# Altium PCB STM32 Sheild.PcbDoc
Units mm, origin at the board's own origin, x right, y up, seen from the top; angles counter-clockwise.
Board outline 70 x 83 mm, 2 copper layers (Top Layer, Bottom Layer), stack 1.712 mm thick; 57 components, 56 nets, 326 pads, 25 vias.
Unrouted connection lines stored in the file: 12.
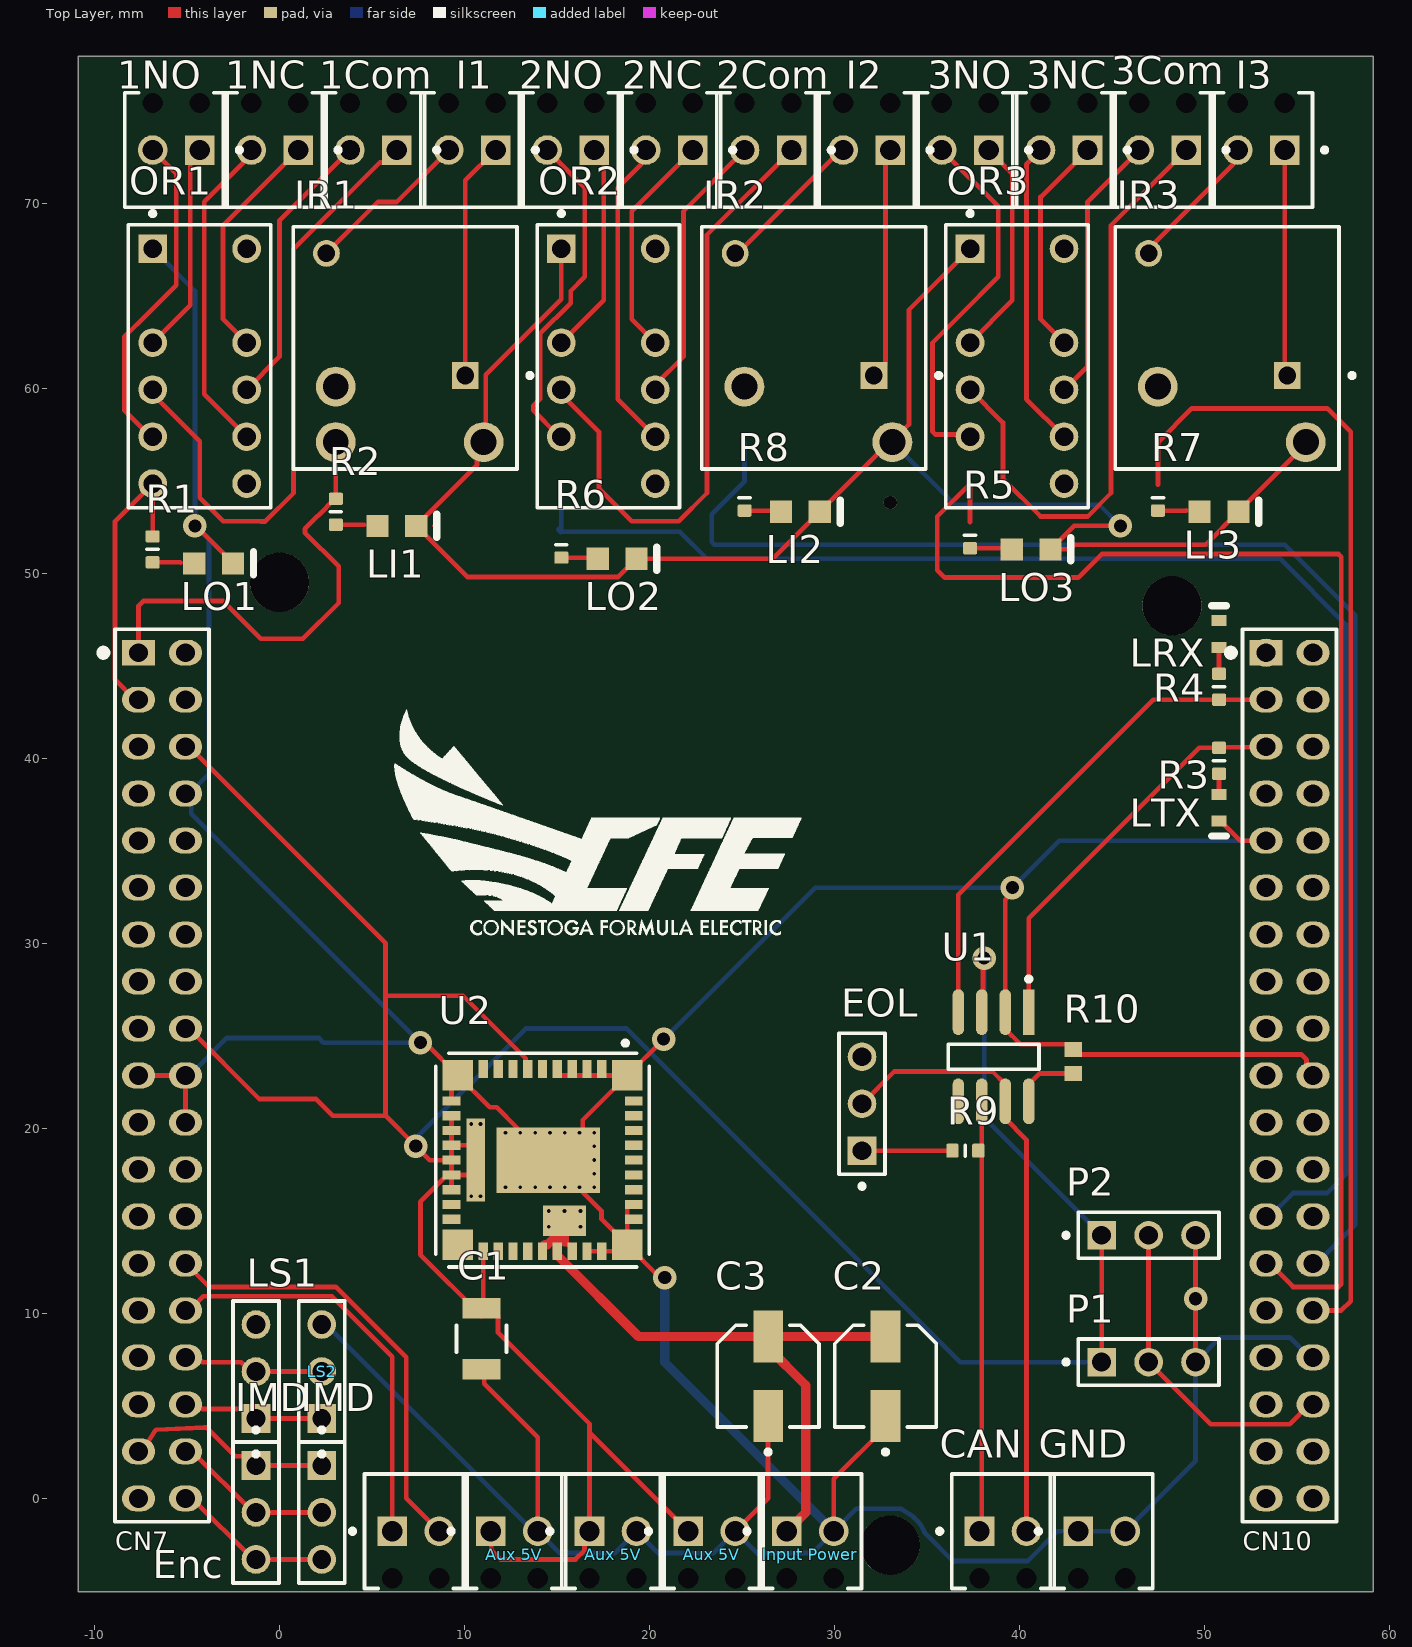
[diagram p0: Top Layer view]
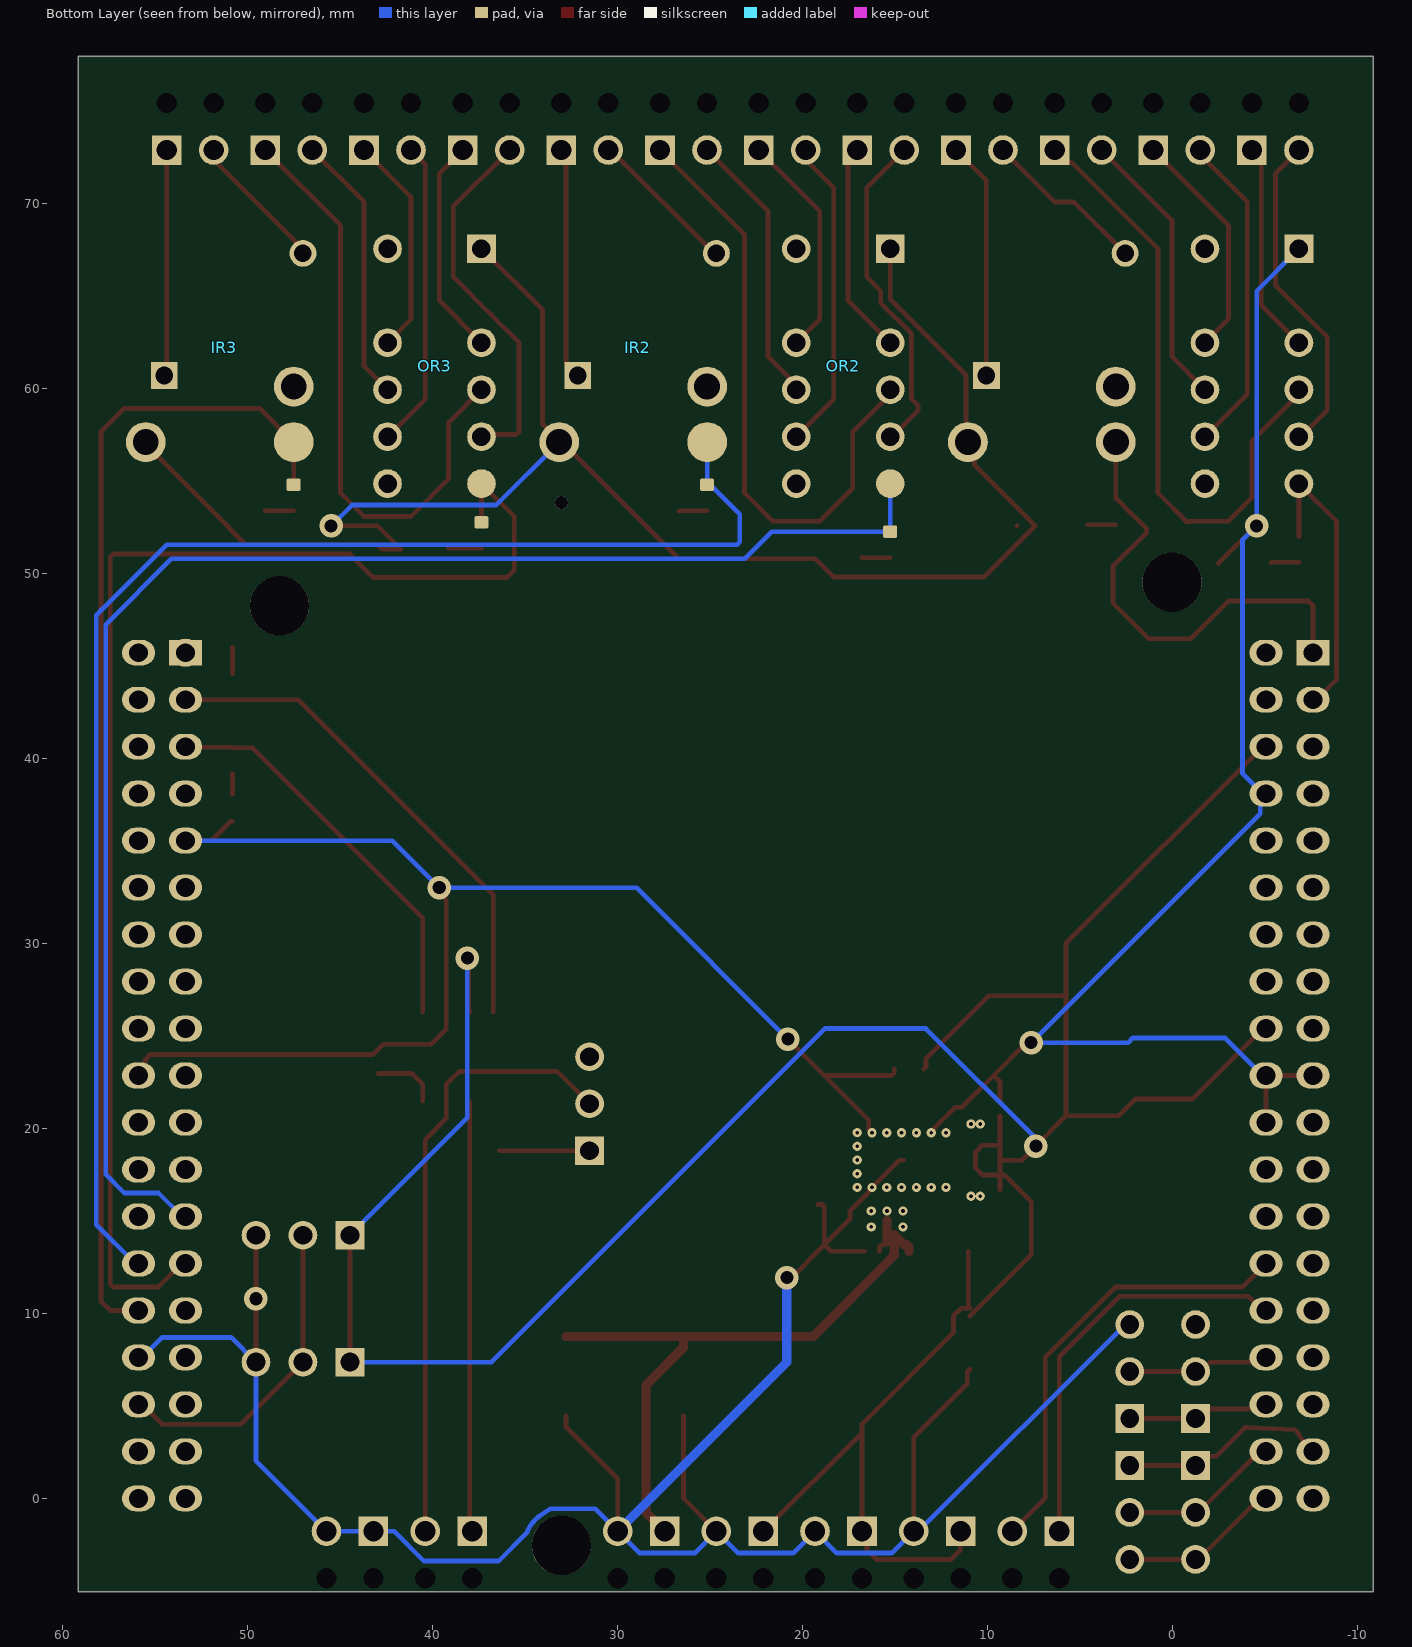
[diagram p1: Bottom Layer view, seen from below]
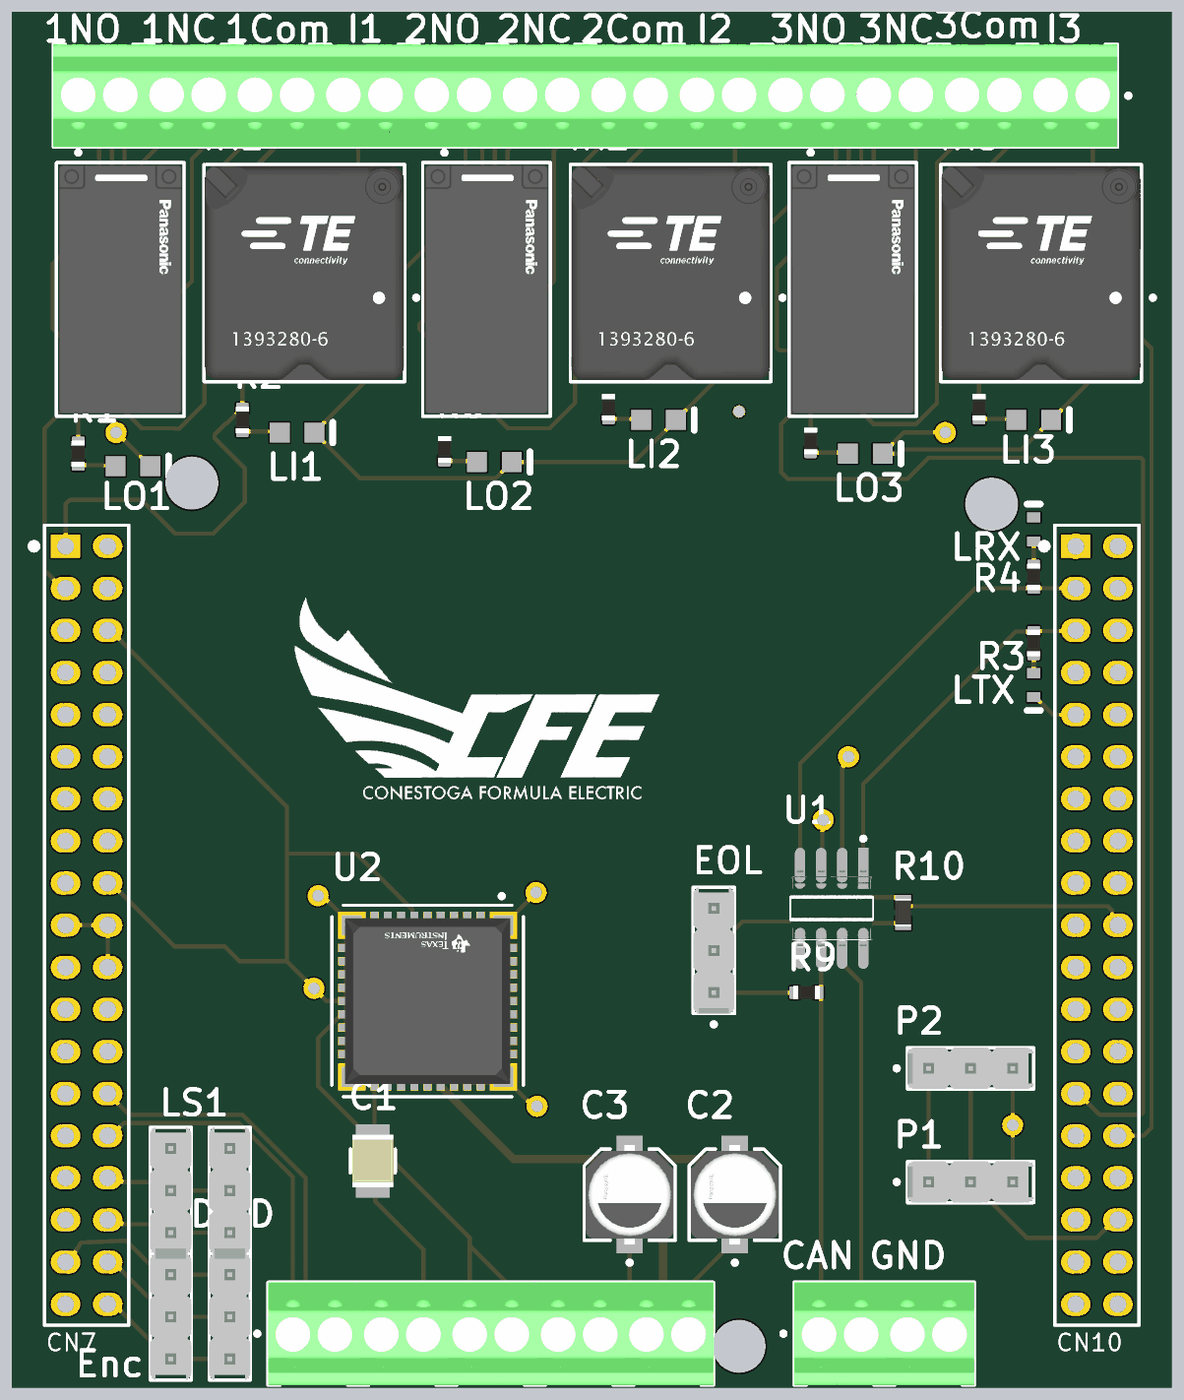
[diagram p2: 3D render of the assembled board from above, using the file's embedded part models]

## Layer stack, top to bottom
Top Solder: solder mask 0.0102, Solder Resist, Dk 3.5
Top Layer: signal copper 0.035
Dielectric 1: prepreg 0.0711, PP-006, Dk 4.1
Dielectric1: core 1.5, FR-4, Dk 4.8
Dielectric 4: prepreg 0.0711, PP-006, Dk 4.1
Bottom Layer: signal copper 0.035
Bottom Solder: solder mask 0.0102, Solder Resist, Dk 3.5

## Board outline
-10.87,-5.04 -10.87,77.96 59.13,77.96 59.13,-5.04 -10.87,-5.04

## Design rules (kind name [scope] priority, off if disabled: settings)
Clearance Clearance_1 [(InPoly)] p1: gap=0.381 ignorepadtopadclearanceinfootprint=FALSE
Clearance Clearance_2 [(HasFootprint('SB_DIP')) or (HasFootprint('JP2_SMD')) or InNet('PC13')] p2: gap=0.127 ignorepadtopadclearanceinfootprint=FALSE
Clearance [All] p3: gap=0.254 ignorepadtopadclearanceinfootprint=FALSE
FabricationTestPointUsage TestPointUsage [All] p1: valid=0 allowmultiple=FALSE
FabricationTestpoint Testpoint [(IsPad And (OnTopLayer Or OnBottomLayer))] p1: side=3 testpointundercomponent=TRUE minsize=1.016 maxsize=2.54 preferedsize=1.524 minholesize=0 maxholesize=1.016 preferedholesize=0.813 testpointgrid=0.025 allowsidetop=TRUE allowsidebottom=TRUE usegrid=TRUE gridtolerance=0
HoleSize [All] p1: absolutevalues=TRUE maxlimit=3.81 minlimit=0.025 maxpercent=80.000 minpercent=20.000
PolygonConnect PolygonConnect_1 [IsVia] p1: connectstyle=Direct reliefconductorwidth=0.508 reliefentries=4 polygonreliefangle="90 Angle" airgapwidth=0.254
PolygonConnect [All] p2: connectstyle=Relief reliefconductorwidth=0.508 reliefentries=4 polygonreliefangle="90 Angle" airgapwidth=0.254
RoutingLayers [All] p1: top layer_v5=FALSE bottom layer_v5=FALSE
RoutingVias [All] p1: holewidth=0.33 width=0.635 viastyle="Through Hole" minholewidth=0.203 minwidth=0.406 maxholewidth=0.711 maxwidth=1.27
SilkToSolderMaskClearance SilkscreenOverComponentPads [IsPad] p1: minsilkscreentomaskgap=0.254 clearancetoexposedcopper=TRUE
SolderMaskExpansion [All] p1: expansion=0.102 istentingtop=FALSE
SupplyNets "Schematic Supply Nets_1" [InNet('+5')] p1: voltage=0.000
SupplyNets "Schematic Supply Nets" [InNet('GND')] p2: voltage=0.000
Width Width_1 [InNet('VDD_MCU')] p1: maxlimit=2.54 minlimit=0.152 preferedwidth=0.305
Width [All] p2: maxlimit=2.54 minlimit=0.254 preferedwidth=0.254 minimp=50.000000 maximp=50.000000 favimp=50.000000
25 further rules are at their usual default settings.

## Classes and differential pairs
component class IMD: IMD
component class "Wheel Speed": "Aux 5V" Enc LS1 LS2
component class "Temp Sensors": P1 P2
component class Power: "5v Regulator" C1 C2 C3 Cin? Cin_? Cout? "Input Power" Rset? U2
component class "GPO Relays": 1Com 1NC 1NO 2Com 2NC 2NO 3Com 3NC 3NO "5v Regulator" Cin? Cin_? Cout? I1 I2 I3 IR1 IR2 IR3 OR1 OR2 OR3 Rset?
component class "MCU Connection": CN7 CN7b CN10 CN10b LI1 LI2 LO1 LO2 LO3 LRX LTX R1 R2 R3 R4 R5 R6 R7 R8
component class Comms: CAN EOL GND R9 R10 U1

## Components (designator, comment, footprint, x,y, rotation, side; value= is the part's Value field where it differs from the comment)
1Com "1725656" PHOE-1725656-2 5.08,72.898 r180 top
1NC "1725656" PHOE-1725656-2 -0.254,72.898 r180 top
1NO "1725656" PHOE-1725656-2 -5.588,72.898 r180 top
2Com "1725656" PHOE-1725656-2 26.416,72.898 r180 top
2NC "1725656" PHOE-1725656-2 21.082,72.898 r180 top
2NO "1725656" PHOE-1725656-2 15.748,72.898 r180 top
3Com "1725656" PHOE-1725656-2 47.752,72.898 r180 top
3NC "1725656" PHOE-1725656-2 42.418,72.898 r180 top
3NO "1725656" PHOE-1725656-2 37.084,72.898 r180 top
"Aux 5V" "1725656" PHOE-1725656-2 12.7,-1.778 r0 top
"Aux 5V" "1725656" PHOE-1725656-2 18.034,-1.778 r0 top
"Aux 5V" "1725656" PHOE-1725656-2 23.368,-1.778 r0 top
C1 "GRM32ER60J107ME20L" FP-GRM32-0_3-MFG 10.922,8.636 r270 top value=100uF
C2 "EEE-FK1H100UR" FP-FKC-MFG 32.766,6.604 r90 top
C3 "EEE-FK1H100UR" FP-FKC-MFG 26.416,6.604 r90 top
CAN "1725656" PHOE-1725656-2 39.116,-1.778 r0 top
CN7 "Header 19X2" 2*19P -7.62,45.72 r270 top locked
CN10 "Header 19X2" 2*19P 53.34,45.72 r270 top locked
Enc "1725656" PHOE-1725656-2 7.366,-1.778 r0 top
EOL "22-28-4033" MOLX-22-28-4033_V 31.496,21.336 r90 top
GND "1725656" PHOE-1725656-2 44.45,-1.778 r0 top
I1 "1725656" PHOE-1725656-2 10.414,72.898 r180 top
I2 "1725656" PHOE-1725656-2 31.75,72.898 r180 top
I3 "1725656" PHOE-1725656-2 53.086,72.898 r180 top
IMD "22-28-4033" MOLX-22-28-4033_V -1.27,-0.762 r270 top
IMD "22-28-4033" MOLX-22-28-4033_V 2.286,-0.762 r270 top
"Input Power" "1725656" PHOE-1725656-2 28.702,-1.778 r0 top
IR1 "1393280-6" FP-1393280-6-MFG#1 6.79,62.2 r180 top
IR2 "1393280-6" FP-1393280-6-MFG#2 28.888,62.2 r180 top
IR3 "1393280-6" FP-1393280-6-MFG#2 51.24,62.2 r180 top
LI1 "HSMG-C170" AVAG-HSMX-C170_V 6.35,52.578 r0 top
LI2 "HSMG-C170" AVAG-HSMX-C170_V 28.16,53.34 r0 top
LI3 "HSMG-C170" AVAG-HSMX-C170_V 50.8,53.34 r0 top
LO1 "HSMG-C170" AVAG-HSMX-C170_V -3.556,50.546 r0 top
LO2 "HSMG-C170" AVAG-HSMX-C170_V 18.254,50.8 r0 top
LO3 "HSMG-C170" AVAG-HSMX-C170_V 40.64,51.308 r0 top
LRX "TLMS1000-GS08" VISH-TLMS1000_V 50.8,46.736 r90 top
LS1 "22-28-4033" MOLX-22-28-4033_V -1.27,6.858 r90 top
LS2 "22-28-4033" MOLX-22-28-4033_V 2.286,6.858 r90 top
LTX "TLMS1000-GS08" VISH-TLMS1000_V 50.8,37.338 r270 top
OR1 "TX2-L2-5V" FP-TX2-L2-5V-MFG#1 -4.318,61.214 r270 top
OR2 "TX2-L2-5V" FP-TX2-L2-5V-MFG#2 17.78,61.214 r270 top
OR3 "TX2-L2-5V" FP-TX2-L2-5V-MFG#2 39.878,61.214 r270 top
P1 "22-28-4033" MOLX-22-28-4033_V 46.99,7.366 r0 top
P2 "22-28-4033" MOLX-22-28-4033_V 46.99,14.224 r0 top
R1 "Resistor 120R +/-5 % 0603 0.1 W" RESC0603(1608)_L#1 -6.858,51.308 r90 top value=120
R2 "Resistor 120R +/-5 % 0603 0.1 W" RESC0603(1608)_L#1 3.048,53.34 r90 top value=120
R3 "Resistor 120R +/-5 % 0603 0.1 W" RESC0603(1608)_L#1 50.8,39.878 r270 top value=120
R4 "Resistor 120R +/-5 % 0603 0.1 W" RESC0603(1608)_L#1 50.8,43.88 r90 top value=120
R5 "Resistor 120R +/-5 % 0603 0.1 W" RESC0603(1608)_L#2 37.338,52.07 r90 top value=120
R6 "Resistor 120R +/-5 % 0603 0.1 W" RESC0603(1608)_L#2 15.24,51.562 r90 top value=120
R7 "Resistor 120R +/-5 % 0603 0.1 W" RESC0603(1608)_L#2 47.498,54.102 r90 top value=120
R8 "Resistor 120R +/-5 % 0603 0.1 W" RESC0603(1608)_L#2 25.146,54.102 r90 top value=120
R9 "Resistor 120R +/-5 % 0603 0.1 W" RESC0603(1608)_L#1 37.084,18.796 r180 top value=120
R10 "CRCW060310K0FKEA" RESC1609X50X30NL8T20 42.926,23.622 r270 top
U1 "SN65HVD230DR" FP-D0008A-IPC_A 38.608,23.876 r270 top
U2 "LMZ34202RVQT" FP-RVQ0043E-MFG 14.224,18.288 r270 top

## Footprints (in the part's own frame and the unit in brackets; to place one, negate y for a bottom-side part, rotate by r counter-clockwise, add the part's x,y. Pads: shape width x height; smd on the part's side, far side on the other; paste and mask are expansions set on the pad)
2*19P [mil]
  rect 55x70 hole 40: 1(0,0)
  oval 55x70 hole 40: 2(0,100) 3(100,0) 4(100,100) 5(200,0) 6(200,100) 7(300,0) 8(300,100) 9(400,0) 10(400,100) 11(500,0) 12(500,100) 13(600,0) 14(600,100) 15(700,0) 16(700,100) 17(800,0) 18(800,100) 19(900,0) 20(900,100) 21(1000,0) 22(1000,100) 23(1100,0) 24(1100,100) 25(1200,0) 26(1200,100) 27(1300,0) 28(1300,100) 29(1400,0) 30(1400,100) 31(1500,0) 32(1500,100) 33(1600,0) 34(1600,100) 35(1700,0) 36(1700,100) 37(1800,0) 38(1800,100)
  silkscreen extent -50,-82 1850,150
AVAG-HSMX-C170_V [mm] "SMD, 2-Leads, Body 2x1.25mm, Height 0.8mm"
  rect 1.2x1.2 smd: 1(-1.05,0) 2(1.05,0)
  silkscreen extent 2.15,-0.63 2.15,0.62, body extent -1,-0.63 1,0.63, height 0.8
FP-1393280-6-MFG#1 [mm]
  rect 1.45x1.45 hole 0.95 paste-2539.97 mask+0: 1(-3.25,1.49)
  round 1.45 hole 0.95 paste-2539.97 mask+0: 2(4.25,-5.11)
  round 2.15 hole 1.4 paste-2539.97 mask+0: 3(3.75,5.09) 4(-4.25,5.09) 5(3.75,2.09)
  silkscreen extent -6.88,-6.55 6.05,6.55, body extent -6.15,-6.65 6.15,6.65, height 0.25
FP-1393280-6-MFG#2 [mm]
  rect 1.45x1.45 hole 0.95 paste-2539.97 mask+0: 1(-3.25,1.49)
  round 1.45 hole 0.95 paste-2539.97 mask+0: 2(4.25,-5.11)
  round 2.15 smd far side paste-2539.97 mask+0: 3(3.75,5.09)
  round 2.15 hole 1.4 paste-2539.97 mask+0: 4(-4.25,5.09) 5(3.75,2.09)
  silkscreen extent -6.88,-6.55 6.05,6.55, body extent -6.15,-6.65 6.15,6.65, height 0.25
FP-D0008A-IPC_A [mm]
  rect 2.469x0.622 smd paste+0 mask+0: 1(-2.414,1.905)
  rrect100% 2.469x0.622 smd paste+0 mask+0: 2(-2.414,0.635) 3(-2.414,-0.635) 4(-2.414,-1.905) 5(2.414,-1.905) 6(2.414,-0.635) 7(2.414,0.635) 8(2.414,1.905)
  silkscreen extent -4.32,-2.45 0.68,2.45, body extent -4.15,-2.95 4.15,2.95, height 0.25
FP-FKC-MFG [mm]
  rect 2.8x1.6 smd paste+0 mask+0: 1(-2.15,0) 2(2.15,0)
  silkscreen extent -4.22,-2.75 2.75,2.75, body extent -3.8,-3 3.8,3, height 0.25
FP-GRM32-0_3-MFG [mm]
  rect 1.1x2.05 smd paste+0 mask+0: 1(-1.65,0) 2(1.65,0)
  silkscreen extent -0.72,-1.35 0.72,1.35, body extent -2.3,-1.45 2.3,1.45, height 0.25
FP-RVQ0043E-MFG [mm]
  rect 1.65x1.65 smd paste-1000 mask+0: 1(-4.575,4.575) 11(-4.575,-4.575) 21(4.575,-4.575) 31(4.575,4.575)
  rect 0.95x0.5 smd paste-1000 mask+0: 2(-4.925,3.2) 3(-4.925,2.4) 4(-4.925,1.6) 5(-4.925,0.8) 6(-4.925,0) 7(-4.925,-0.8) 8(-4.925,-1.6) 9(-4.925,-2.4) 10(-4.925,-3.2) 22(4.925,-3.2) 23(4.925,-2.4) 24(4.925,-1.6) 25(4.925,-0.8) 26(4.925,0) 27(4.925,0.8) 28(4.925,1.6) 29(4.925,2.4) 30(4.925,3.2)
  rect 0.5x0.95 smd paste-1000 mask+0: 12(-3.2,-4.925) 13(-2.4,-4.925) 14(-1.6,-4.925) 15(-0.8,-4.925) 16(0,-4.925) 17(0.8,-4.925) 18(1.6,-4.925) 19(2.4,-4.925) 20(3.2,-4.925) 32(3.2,4.925) 33(2.4,4.925) 34(1.6,4.925) 35(0.8,4.925) 36(0,4.925) 37(-0.8,4.925) 38(-1.6,4.925) 39(-2.4,4.925) 40(-3.2,4.925)
  rect 3.55x5.6 smd paste-1000 mask-1000: 41(0,0.3)
  rect 1.65x2.32 smd paste-1000 mask-1000: 42(3.275,1.187)
  rect 4.5x1 smd paste-1000 mask-1000: 43(0,-3.6)
  round 0.5 hole 0.2 paste-2539.97 mask+0: ""(-1.95,-3.85) ""(-1.95,-3.35) ""(-1.485,2.8) ""(-1.475,-2) ""(-0.745,2.8) ""(-0.005,2.8) ""(0.735,2.8) ""(1.475,2.8) ""(1.475,-2) ""(1.95,-3.85) ""(1.95,-3.35)
  silkscreen extent -6.45,-5.77 5.77,5.77, body extent -5.5,-5.5 5.5,5.5, height 0.25
FP-TX2-L2-5V-MFG#1 [mm]
  rect 1.55x1.55 hole 1 paste-2539.97 mask+0: 1(-6.35,-2.54)
  round 1.55 hole 1 paste-2539.97 mask+0: 3(-1.27,-2.54) 4(1.27,-2.54) 5(3.81,-2.54) 6(6.35,-2.54) 7(6.35,2.54) 8(3.81,2.54) 9(1.27,2.54) 10(-1.27,2.54) 12(-6.35,2.54)
  silkscreen extent -8.37,-3.85 7.65,3.85, body extent -7.75,-3.95 7.75,3.95, height 0.25
FP-TX2-L2-5V-MFG#2 [mm]
  rect 1.55x1.55 hole 1 paste-2539.97 mask+0: 1(-6.35,-2.54)
  round 1.55 hole 1 paste-2539.97 mask+0: 3(-1.27,-2.54) 4(1.27,-2.54) 5(3.81,-2.54) 7(6.35,2.54) 8(3.81,2.54) 9(1.27,2.54) 10(-1.27,2.54) 12(-6.35,2.54)
  round 1.55 smd far side paste-2539.97 mask+0: 6(6.35,-2.54)
  silkscreen extent -8.37,-3.85 7.65,3.85, body extent -7.75,-3.95 7.75,3.95, height 0.25
MOLX-22-28-4033_V [mm] "THD, 3-Leads, Body 7.62x2.49mm, Pitch 2.54mm"
  rect 1.55x1.55 hole 1.02: 1(-2.54,0)
  round 1.55 hole 1.02: 2(0,0) 3(2.54,0)
  silkscreen extent -4.58,-1.24 3.81,1.24, body extent -3.81,-1.24 3.81,1.24, height 8.38
PHOE-1725656-2 [mm] "Connector, 2-Leads, Body 6.2x5.4mm, Pitch 2.54mm"
  rect 1.6x1.6 hole 1.1: 1(-1.27,0)
  round 1.6 hole 1.1: 2(1.27,0)
  round 0 hole 1.1 unplated: MH1(-1.27,-2.54) MH2(1.27,-2.54)
  silkscreen extent -3.55,-3.1 2.77,3.1, body extent -2.77,-3.1 2.77,3.1, height 9
RESC0603(1608)_L#1 [mm] "Chip Resistor, Body 1.6x0.8mm, IPC High Density"
  rrect25% 0.66x0.76 smd: 1(-0.7,0) 2(0.7,0)
  silkscreen extent 0,-0.3 0,0.3, body extent -0.8,-0.4 0.8,0.4, height 0.45
RESC0603(1608)_L#2 [mm] "Chip Resistor, Body 1.6x0.8mm, IPC High Density"
  rrect25% 0.66x0.76 smd: 1(-0.7,0)
  rrect25% 0.66x0.76 smd far side: 2(0.7,0)
  silkscreen extent 0,-0.3 0,0.3, body extent -0.8,-0.4 0.8,0.4, height 0.45
RESC1609X50X30NL8T20 [mm] "Chip Resistor, 2-Leads, Body 1.65x0.95mm, IPC Medium Density"
  rect 0.8x0.95 smd: 1(-0.65,0) 2(0.65,0)
  body extent -0.82,-0.48 0.82,0.48, height 0.5
VISH-TLMS1000_V [mm] "SMD, 2-Leads, Body 0.8x1.6mm"
  rect 0.6x0.8 smd: 1(-0.725,0) 2(0.725,0)
  silkscreen extent 1.53,-0.4 1.53,0.4, body extent -0.8,-0.4 0.8,0.4, height 0.65

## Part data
1Com 1NC 1NO 2Com 2NC 2NO 3Com 3NC 3NO "Aux 5V" "Aux 5V" "Aux 5V" CAN Enc GND I1 I2 I3 "Input Power": library part CMP-2000-05299-1, "Male Header, Pitch 2.54 mm, 1 x 2 Position, Height 9 mm, Tail Length 3.5 mm", Colour=Green, Manufacturer="Phoenix Contact"
C1: library part CMP-2000-05259-2, "CAP CER 100UF 6.3V X5R 1210", 3DS Part Number=220-00002, Capacitance=100uF, Manufacturer=Murata, Package=GRM32-0.3, Temperature="-55°C to +85°C", Temperature Characteristic=X5R, Temperature Coefficient=15%, Temperature Range High=+85°C, Temperature Range Low=-55°C, Tolerance=20%, Voltage=6.3V
C2 C3: library part CMP-05427-000030-1, "CAP ALUM 10UF 20% 50V SMD", Capacitance=10uF, Case/Package=Radial, Dielectric Material=Aluminium, ESR (Equivalent Series Resistance)=1.52R, Leakage Current=3uA, Max Operating Temperature=105°C, Min Operating Temperature=-55°C, Package Quantity=1000, Ripple Current=85mA, Tolerance=20%, Voltage=50V
CN7 CN10: library part SSW-119-01-T-D, "Connector", Manufacturer_Name=SAMTEC, Mouser Part Number=200-SSW11901TD
EOL IMD IMD LS1 LS2 P1 P2: library part CMP-1676-00001-5, "Male Header, Pitch 2.54 mm, 1 x 3 Position, Height 8.38 mm, Tail Length 3.18 mm, RoHS, Bulk", Colour=Black, Current Rating="4 A", Manufacturer=Molex, Max Operating Temperature="75 degC", Min Operating Temperature="0 degC", Package Quantity=1, Voltage Rating="250 V"
IR1 IR2 IR3: library part CMP-03395-000123-1, "Electromechanical Relay 12VDC 254Ohm 40A SPDT (12.9x12x9.9)mm THT Power Relay", Ambient Temperature Range High=+105°C, Ambient Temperature Range Low=-40°C, Coil Power=567mW, Coil Resistance=254Ω, Coil Voltage=12V, Current Rating=30A, Manufacturer="TE Connectivity"
LI1 LI2 LI3 LO1 LO2 LO3: library part CMP-2000-05062-1, "Chip LED, Green, 2.2 V, -40 to 85 degC, 2-Pin SMD, Pb-Free, Tape and Reel", Forward Current If=20mA, Forward Voltage=2.2V, Forward Voltage VF Max=2.6V, LED Colour=Green, Manufacturer=Avago, Operating Temperature Max=85degC, Operating Temperature Min=-30degC, Operating Temperature Range=-30degCto+85degC, Opto Case Style=SMD, Package Description="2-Pin Surface Mount Device, Body 2 x 1.25 mm, Height 0.8 mm", Package Reference=HSMX-C170, Storage Temperature Min=-40degC
LRX LTX: library part CMP-2000-07254-1, "Low Current LED, 40 mW, 1.8 V, -40 to 100 degC, 2-Pin SMD (0603), RoHS, Tape and Reel", Forward Current If=2mA, Forward Voltage=1.8V, LED Colour=Red, Manufacturer=Vishay, Package Description="2-Pin Surface Mount Device, Body 1.6 x 0.8 mm", Package Reference=TLMS1000
OR1 OR2 OR3: library part CMP-00287-39525588-1, "TX2-L2-5V Telecom Relay DPDT (2 Form C) Latching Double Coil 5VDC 2A Through Hole 125 Ohm", Case/Package=DIP, Coil Current=40mA, Coil Power=200mW, Coil Resistance=125Ω, Coil Voltage (DC)=5V, Contact Current Rating=2A, Max Operating Temperature=85°C, Max Voltage Rating (DC)=220V, Min Operating Temperature=-40°C, Power Rating=60W, Ratings=IP67, Test Voltage=2kV
R1 R2 R3 R4 R5 R6 R7 R8 R9: library part CMP-009-00176-3, "Chip Resistor, 120 Ohms, +/-5 %, 0.1 W, -55 to 155 degC, 0603", Case/Package=0603, Max Operating Temperature=155°C, Min Operating Temperature=-55°C, Power=100mW, Tolerance=5%
R10: library part CMP-1666-00005-4, "Chip Resistor, 10 KOhm, +/- 1%, 100 mW, -55 to 155 degC, 0603 (1608 Metric), RoHS, Tape and Reel", Manufacturer="Vishay Semiconductor", Max Operating Temperature="155 degC", Min Operating Temperature="-55 degC", Package Quantity=5000, Voltage Rating="75 V"
U1: library part CMP-0315-00015-3, "IC TRANSCEIVER HALF 1/1 8SOIC", Case/Package=D, Max Operating Temperature=85°C, Max Supply Current=17mA, Max Supply Voltage=3.6V, Min Operating Temperature=-40°C, Min Supply Voltage=3V, Operating Supply Voltage=3.3V, Package Quantity=1
U2: library part CMP-04918-000024-1, "DC DC CONVERTER 2.5-7.5V 2A", Ambient Temperature Range High=+105°C, Ambient Temperature Range Low=-40°C, Manufacturer="Texas Instruments", Max Junction Temp=+125°C, Max Supply Voltage=42V, Min Supply Voltage=4.5V, Nominal Supply Current=0.6mA, Output Current=2A, Output Voltage=2.5-7.5V, Package=RVQ0043E, Switching Frequency=300-1000kHz, Temperature="-40°C to +105°C"

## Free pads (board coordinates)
  round 3.2 hole 3.2 unplated: 0(0,49.53) 0(33.02,-2.54) 0(48.26,48.26)
  round 1.524 hole 0.762: 2(53.34,45.72)

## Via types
v1: diameter 0.5, hole 0.2, Top Layer to Bottom Layer, 15 vias
v2: diameter 1.27, hole 0.711, Top Layer to Bottom Layer, 9 vias
v3: diameter 0.711, hole 0.711, Top Layer to Bottom Layer, 1 vias

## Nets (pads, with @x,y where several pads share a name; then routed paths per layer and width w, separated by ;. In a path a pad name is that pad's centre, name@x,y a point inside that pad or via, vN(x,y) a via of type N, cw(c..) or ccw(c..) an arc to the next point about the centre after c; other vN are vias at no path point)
+5: "Aux 5V.1" C1.1 CN7.6 CN7.18 P1.1 P2.1 U1.3 U2.7 U2.13 U2.14 U2.15 U2.16 U2.17 U2.18 U2.22 U2.43 | length 176.8
  Top Layer w0.254: CN7.18 -4.889,25.4 -1.079,21.59 1.988,21.59 2.89,20.688 5.737,20.688 ; CN7.6 -4.889,40.64 5.737,30.014 5.737,20.679 v2(7.366,19.05) 8.128,18.288 U2.16 ; 5.737,27.178 9.923,27.178 13.301,23.8 13.301,23.336 U2.7 ; U2.18 U2.17 ; U2.13 U2.14 U2.15 ; C1.1@10.922,9.862 7.62,13.164 7.62,16.034 9.074,17.488 U2.17 ; U2.22 11.024,10.388 C1.1 11.397,10.286 11.82,9.863 11.82,8.964 16.764,4.02 16.764,3.556 ; 11.43,-1.778 11.446,-1.794 11.446,-2.81 11.938,-3.302 16.002,-3.302 16.494,-2.81 16.494,-2.048 16.764,-1.778 16.764,3.556 ; 22.098,-1.778 16.764,3.556 ; U1.3 38.037,26.353 38.037,29.147 v2(38.1,29.21) ; P1.1 P2.1 ; U2.17 10.251,17.488 10.624,17.861 U2.43 10.624,18.715 10.251,19.088 U2.15 ; U2.17 U2.16 ; U2.16 U2.15
  Bottom Layer w0.254: v2@7.366,19.304 7.366,19.458 13.308,25.4 18.767,25.4 36.801,7.366 P1.1 ; v2(38.1,29.21) 38.1,20.574 P2.1
GND: "Aux 5V.2" "Input Power.2" C1.2 C2.1 C3.1 CN7.8 CN7.19 CN7.20 CN7.22 CN10.9 CN10.20 CN10.32 GND.1 GND.2 IR1.4 IR2.4 IR3.4 LI1.2 LI2.2 LI3.2 LO1.2 LO2.2 LO3.2 LRX.2 LS1.3 LS2.3 LTX.2 OR1.1 OR2.1 OR3.1 P1.3 P2.3 R10.1 U1.2 U2.1 U2.2 U2.3 U2.4 U2.5 U2.11 U2.12 U2.19 U2.29 U2.30 U2.31 U2.32 U2.33 U2.41 | length 386.8
  Top Layer w0.254: CN7.19 CN7.20 CN7.22 ; v2(-4.572,52.578) -4.538,52.578 LO1.2 ; v2(7.62,24.638) 7.874,24.638 U2.11 ; U2.12 9.299,22.513 U2.11 ; C1.2 11.068,6.84 11.068,6.204 13.97,3.302 13.97,-1.778 ; v1(13.024,19.763) 12.855,19.932 12.855,20.024 11.736,21.144 11.368,21.144 U2.11 ; U2.41 14.745,18.288 16.393,16.64 16.393,16.552 16.726,16.219 16.729,16.219 17.415,15.533 17.415,15.097 U2.31 ; U2.5 15.024,22.988 15.149,22.863 U2.1 ; OR2.1 15.24,64.837 11.146,60.743 11.146,57.216 IR1.4 10.677,56.747 10.677,55.855 LI1.2 10.159,49.819 18.323,49.819 LO2.2 26.67,50.8 LI2.2 32.98,57.11 IR2.4 33.138,57.163 34.036,58.061 34.036,64.262 OR3.1 ; U2.41@16.222,19.765 16.393,19.936 16.393,20.457 U2.1 ; U2.29 U2.30 18.449,13.363 U2.31 ; U2.33 18.924,15.888 18.799,15.763 U2.31 ; v2(20.77,24.834) U2.1 ; v2(20.828,11.938) 20.574,11.938 U2.31 ; 24.638,-1.778 26.416,0 C3.1 ; 29.972,-1.778 29.972,1.06 32.766,3.854 C2.1 ; v2(39.624,33.02) 39.624,32.745 39.243,32.364 U1.2 39.243,25.366 40.064,24.545 42.653,24.545 R10.1 43.199,23.999 55.249,23.999 55.529,23.719 55.529,23.211 CN10.20 ; v2(45.466,52.578) 42.96,52.578 LO3.2 42.71,51.308 42.964,51.562 50.072,51.562 LI3.2 55.49,56.98 IR3.4 ; P1.3 v2(49.53,10.795) P2.3 ; LTX.2 50.9,36.613 51.953,35.56 CN10.9
  Bottom Layer w0.254: OR1.1 -4.572,65.278 v2(-4.572,52.578) -3.81,51.816 -3.81,39.18 -4.889,38.1 CN7.8 -4.763,37.783 -4.763,37.021 v2(7.62,24.638) 2.371,24.638 2.117,24.892 -2.858,24.892 -4.889,22.86 CN7.20 ; LS2.3 2.54,9.398 13.716,-1.778 13.97,-1.778 15.151,-2.959 18.123,-2.959 19.304,-1.778 20.485,-2.959 23.457,-2.959 24.638,-1.778 25.819,-2.959 28.791,-2.959 29.972,-1.778 31.191,-0.559 33.579,-0.559 34.056,-0.851 cw(c33.02,-2.54) 34.881,-1.861 36.407,-3.387 40.447,-3.387 42.056,-1.778 GND.1 GND.2 49.53,2.032 P1.3 50.864,8.7 54.61,8.7 55.69,7.62 CN10.32 ; v2(20.77,24.834) 28.956,33.02 v2(39.624,33.02) 42.164,35.56 CN10.9 ; IR2.4 36.54,53.708 44.336,53.708 v2(45.466,52.578)
  Bottom Layer w0.5: v2(20.828,11.938) 20.828,7.366 29.972,-1.778
  other v1: 13.024,16.813 13.824,16.813 14.624,16.813 15.424,16.813 16.224,16.813 13.824,19.763 14.624,19.763 15.424,19.763 16.224,19.763
Net1Com_1: 1Com.1 OR1.4 | length 34.2
  Top Layer w0.254: OR1.4 -6.858,59.69 -4.779,57.611 -4.318,57.15 -4.318,54.102 -3.048,52.832 -1.016,52.832 -0.994,52.81 -0.784,52.81 0.762,54.356 0.762,67.564 5.423,72.225 5.677,72.225 1Com.1
Net1Com_2: 1Com.2 OR1.9 | length 15.3
  Top Layer w0.254: OR1.9 0,61.722 0,69.088 1Com.2
Net1NC_1: 1NC.1 OR1.10 | length 12.6
  Top Layer w0.254: OR1.10 -3.048,63.754 -3.048,68.834 1NC.1
Net1NC_2: 1NC.2 OR1.8 | length 17.5
  Top Layer w0.254: OR1.8 -4.064,59.69 -4.064,70.104 -1.524,72.644 1NC.2
Net1NO_1: 1NO.1 OR1.3 | length 11.5
  Top Layer w0.254: OR1.3 -4.826,64.516 -4.826,72.39 1NO.1
Net1NO_2: 1NO.2 OR1.5 | length 17.9
  Top Layer w0.254: OR1.5@-6.858,57.404 cw(c-6.854,57.658) -7.039,57.483 -8.382,58.826 -8.382,60.872 -8.382,62.194 -8.382,62.797 -7.956,63.222 -7.53,63.648 -5.588,65.591 -5.588,71.628 -5.662,71.702 1NO.2
Net2Com_1: 2Com.1 OR2.4 | length 33.8
  Top Layer w0.254: OR2.4 15.24,59.69 17.272,57.658 17.272,54.61 19.05,52.832 21.59,52.832 23.114,54.356 23.114,68.326 2Com.1
Net2Com_2: 2Com.2 OR2.9 | length 14.9
  Top Layer w0.254: OR2.9 20.32,60.198 21.844,61.722 21.844,69.596 2Com.2@25.13,72.882
Net2NC_1: 2NC.1 OR2.10 | length 12.3
  Top Layer w0.254: OR2.10 19.05,63.754 19.05,69.596 2NC.1
Net2NC_2: 2NC.2 OR2.8 | length 17
  Top Layer w0.254: 2NC.2 19.554,72.64 19.554,72.132 18.288,70.866 18.288,59.436 OR2.8
Net2NO_1: 2NO.1 OR2.3 | length 11.6
  Top Layer w0.254: OR2.3 17.526,64.77 17.526,72.39 2NO.1
Net2NO_2: 2NO.2 OR2.5 | length 18.2
  Top Layer w0.254: 2NO.2 16.51,70.866 16.51,66.04 15.748,65.278 15.748,64.627 14.084,62.963 14.084,59.436 13.716,59.068 13.716,58.826 15.059,57.483 ccw(c15.244,57.658) OR2.5@15.24,57.404
Net3Com_1: 3Com.1 OR3.4 | length 33
  Top Layer w0.254: OR3.4 39.116,58.166 39.116,55.118 41.148,53.086 43.688,53.086 44.958,54.356 44.958,68.834 3Com.1
Net3Com_2: 3Com.2 OR3.9 | length 14.6
  Top Layer w0.254: OR3.9 43.688,61.214 43.688,70.104 3Com.2
Net3NC_1: 3NC.1 OR3.10 | length 12
  Top Layer w0.254: OR3.10 41.148,63.754 41.148,70.358 3NC.1
Net3NC_2: 3NC.2 OR3.8 | length 16.7
  Top Layer w0.254: 3NC.2 40.386,72.136 40.386,59.436 OR3.8
Net3NO_1: 3NO.1 OR3.3 | length 11.9
  Top Layer w0.254: OR3.3 39.624,64.77 39.624,71.628 3NO.1
Net3NO_2: 3NO.2 OR3.5 | length 20.1
  Top Layer w0.254: 3NO.2 38.862,69.85 38.862,66.04 36.801,63.979 35.306,62.484 35.306,60.369 35.306,57.672 35.455,57.524 37.218,57.524 OR3.5
NetC2_2: "Input Power.1" C2.2 C3.2 U2.26 U2.27 U2.28 U2.42 | length 35.7
  Top Layer w0.254: 15.411,13.86 15.56,13.711 15.701,13.711 15.824,13.588 U2.28
  Top Layer w0.5: U2.26 14.224,13.588 14.347,13.711 14.476,13.711 15.024,14.259 15.024,13.138 19.408,8.754 C3.2 ; 15.411,13.86 U2.42 ; 27.432,-1.778 28.448,-0.762 28.448,6.122 26.416,8.154 C3.2 ; C2.2 C3.2
  other v1: 14.551,14.678 16.271,14.678 14.551,15.538 15.411,15.538 16.271,15.538
NetCAN_1: CAN.1 R9.1 U1.6 | length 23.3
  Top Layer w0.254: CAN.1 37.973,-1.651 U1.6
NetCAN_2: CAN.2 EOL.2 U1.7 | length 33.4
  Top Layer w0.254: EOL.2 33.238,23.078 38.551,23.078 39.243,22.386 U1.7 39.243,20.539 40.386,19.396 CAN.2
NetCN7_1: CN7.1 IR1.3 R2.2 | length 25.6
  Top Layer w0.254: CN7.1 -7.62,48.26 -7.366,48.514 -3.048,48.514 -1.016,46.482 1.27,46.482 3.197,48.409 3.197,50.397 1.375,52.219 1.375,52.429 2.079,53.133 2.091,53.133 2.998,54.04 R2.2 3.044,54.044 3.044,57.106 IR1.3 ; R2.2@2.798,53.837 3.005,54.044 R2.2@3.04,54.044
NetCN7_3: CN7.3 OR1.6 R1.2 | length 16
  Top Layer w0.254: CN7.3 -7.81,43.18 -8.89,44.26 -8.89,52.832 OR1.6 R1.2
NetCN7_28: CN7.28 Enc.2 | length 24.2
  Top Layer w0.254: CN7.28 -3.81,11.43 3.048,11.43 6.858,7.62 6.858,0 Enc.2
NetCN7_30: CN7.30 Enc.1 | length 22.3
  Top Layer w0.254: CN7.30 -4.887,10.16 -4.125,10.922 2.838,10.922 6.096,7.664 Enc.1
NetCN7_32: CN7.32 LS1.2 LS2.2 | length 7.7
  Top Layer w0.254: CN7.32 -4.861,7.401 -4.205,7.401 -4.169,7.366 -2.067,7.366 -1.559,6.858 LS2.2
NetCN7_34: CN7.34 LS1.1 LS2.1 | length 7.7
  Top Layer w0.254: CN7.34 -4.861,4.861 -4.205,4.861 -4.169,4.826 -1.778,4.826 LS1.1 LS2.1
NetCN7_35: CN7.35 IMD.1 | length 11.4
  Top Layer w0.254: CN7.35 -7.429,2.54 -6.761,3.602 -6.746,3.627 -6.656,3.716 -4.058,3.833 -3.947,3.833 -2.391,2.277 -1.769,2.277 -1.27,1.778 IMD.1@2.286,1.778
NetCN7_36: CN7.36 IMD.2 | length 8.7
  Top Layer w0.254: CN7.36 -4.731,2.54 -1.429,-0.762 -1.27,-0.762 IMD.2@2.286,-0.762
NetCN7_38: CN7.38 IMD.3 | length 8.7
  Top Layer w0.254: CN7.38 -4.731,0 -1.429,-3.302 -1.27,-3.302 IMD.3@2.286,-3.302
NetCN10_3: CN10.3 R4.1 U1.4 | length 27.4
  Top Layer w0.254: U1.4 36.703,32.639 47.244,43.18 R4.1 CN10.3@53.34,43.18
NetCN10_5: CN10.5 R3.1 U1.1 | length 21.7
  Top Layer w0.254: U1.1 40.513,31.369 49.722,40.578 R3.1 50.831,40.609 53.309,40.609 CN10.5
NetCN10_25: CN10.25 OR2.6 R6.2 | length 82.5
  Bottom Layer w0.254: R6.2@15.211,52.241 15.081,52.371 R6.2@15.24,52.53 ; R6.2@15.236,52.266 15.24,52.27 R6.2@15.24,52.53 ; R6.2 21.652,52.262 23.114,50.8 54.102,50.8 57.658,47.244 57.658,17.526 56.642,16.51 54.8,16.51 53.531,15.24 CN10.25 ; OR2.6 R6.2@15.24,52.53
NetCN10_27: CN10.27 OR3.6 R5.2 | length 74.1
  Top Layer w0.254: 37.338,52.77 37.338,54.864 35.56,53.086 35.56,50.187 35.963,49.784 43.18,49.784 44.45,51.054 57.255,51.054 57.404,50.905 57.404,11.579 57.255,11.43 54.801,11.43 53.531,12.7 CN10.27
NetCN10_28: CN10.28 IR2.3 R8.2 | length 78.7
  Bottom Layer w0.254: IR2.3 25.138,54.964 23.368,53.194 23.368,51.711 23.517,51.562 54.356,51.562 58.166,47.752 58.166,14.796 56.071,12.7 CN10.28 ; 57.912,48.006 57.912,48.05
NetCN10_30: CN10.30 IR3.3 R7.2 | length 63.2
  Top Layer w0.254: 47.498,54.802 47.494,54.806 47.494,57.106 47.49,57.11 47.504,57.11 49.322,58.928 56.642,58.928 57.912,57.658 57.912,10.668 57.404,10.16 CN10.30
NetCN10_34: CN10.34 P1.2 P2.2 | length 17.6
  Top Layer w0.254: P2.2 P1.2 50.355,4.001 54.61,4.001 55.69,5.08 CN10.34
NetEOL_1: EOL.1 R9.2 | length 4.9
  Top Layer w0.254: EOL.1 R9.2
NetI1_1: I1.1 IR1.1 | length 12.9
  Top Layer w0.254: IR1.1 10.04,71.254 I1.1
NetI1_2: I1.2 IR1.2 | length 8.9
  Top Layer w0.254: IR1.2 5.32,70.09 6.336,70.09 I1.2
NetI2_1: I2.1 IR2.1 | length 12.6
  Top Layer w0.254: IR2.1 32.736,61.308 32.736,61.427 32.766,61.457 32.766,72.644 I2.1
NetI2_2: I2.2 IR2.2 | length 8.2
  Top Layer w0.254: IR2.2 24.765,67.31 30.353,72.898 I2.2
NetI3_1: I3.1 IR3.1 | length 12.2
  Top Layer w0.254: I3.1 54.356,60.844 IR3.1
NetI3_2: I3.2 IR3.2 | length 7.6
  Top Layer w0.254: IR3.2 46.99,67.564 51.558,72.132 51.558,72.64 I3.2
NetLI1_1: LI1.1 R2.1 | length 1.5
  Top Layer w0.254: R2.1 4.566,52.64 4.572,52.646
NetLI2_1: LI2.1 R8.1 | length 1.5
  Top Layer w0.254: R8.1 26.642,53.402 LI2.1@26.67,53.374
NetLI3_1: LI3.1 R7.1 | length 1.5
  Top Layer w0.254: R7.1 49.016,53.402 49.022,53.408
NetLO1_1: LO1.1 R1.1 | length 1.6
  Top Layer w0.254: R1.1@-6.808,50.608 R1.1 -5.362,50.608 -5.334,50.58
NetLO2_1: LO2.1 R6.1 | length 1.5
  Top Layer w0.254: R6.1 16.758,50.862 LO2.1@16.764,50.868
NetLO3_1: LO3.1 R5.1 | length 1.8
  Top Layer w0.254: R5.1 39.11,51.37 LO3.1@39.116,51.376
NetLRX_1: LRX.1 R4.2 | length 1.4
  Top Layer w0.254: R4.2 LRX.1
NetLTX_1: LTX.1 R3.2 | length 1.1
  Top Layer w0.254: LTX.1 R3.2
NetR10_2: R10.2 U1.8 | length 3.6
  Top Layer w0.254: U1.8 40.513,22.386 41.099,22.972 R10.2
NetRset1_2: U2.23 U2.24
pads on no net: 1Com.MH1 1Com.MH2 1NC.MH1 1NC.MH2 1NO.MH1 1NO.MH2 2Com.MH1 2Com.MH2 2NC.MH1 2NC.MH2 2NO.MH1 2NO.MH2 3Com.MH1 3Com.MH2 3NC.MH1 3NC.MH2 3NO.MH1 3NO.MH2 "Aux 5V.MH1" "Aux 5V.MH2" "Input Power.MH1" "Input Power.MH2" CAN.MH1 CAN.MH2 CN7.2 CN7.4 CN7.5 CN7.7 CN7.9 CN7.10 CN7.11 CN7.12 CN7.13 CN7.14 CN7.15 CN7.16 CN7.17 CN7.21 CN7.23 CN7.24 CN7.25 CN7.26 CN7.27 CN7.29 CN7.31 CN7.33 CN7.37 CN10.1 CN10.2 CN10.4 CN10.6 CN10.7 CN10.8 CN10.10 CN10.11 CN10.12 CN10.13 CN10.14 CN10.15 CN10.16 CN10.17 CN10.18 CN10.19 CN10.21 CN10.22 CN10.23 CN10.24 CN10.26 CN10.29 CN10.31 CN10.33 CN10.35 CN10.36 CN10.37 CN10.38 Enc.MH1 Enc.MH2 EOL.3 GND.MH1 GND.MH2 I1.MH1 I1.MH2 I2.MH1 I2.MH2 I3.MH1 I3.MH2 IR1.5 IR2.5 IR3.5 OR1.7 OR1.12 OR2.7 OR2.12 OR3.7 OR3.12 U1.5 U2. U2.6 U2.8 U2.9 U2.10 U2.20 U2.21 U2.25 U2.34 U2.35 U2.36 U2.37 U2.38 U2.39 U2.40
copper on no net: | length 0
  other v3: 33.02,53.848

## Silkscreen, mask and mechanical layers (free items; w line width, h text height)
Top Overlay:
  drawing of 28 lines, arcs and shapes, not listed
